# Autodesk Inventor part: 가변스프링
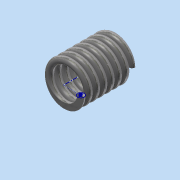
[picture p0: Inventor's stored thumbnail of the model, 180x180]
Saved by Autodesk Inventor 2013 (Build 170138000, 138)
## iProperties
Created: 2019-11
Part Number: 가변스프링
Material: 스테인리스강
Document SubType Name: Modeling
Designer: Administrator
Density: 8.08 g/cm^3
Mass: 19.5517 g
Surface Area: 32.9547 cm^2
Volume: 2.41976 cm^3
Author: Administrator
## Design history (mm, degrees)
sketch "스케치1"
  geometry: L1 (0, 0)-(8, 0); L2 (8, 0)-(8, 23.5); L3 (8, 23.5)-(0, 23.5); L4 (0, 23.5)-(0, 0); C1 r 1.5 at (8, 0)
  constraints: 8 end point, 2 parallel, 1 centre point, 1 coincident, 1 horizontal, 1 perpendicular
  dimensions: "d0" = 16 diameter of L2 L4; "d2" = 23.5 distance between parallel lines of L1 L3 (derived); "d3" = 3 diameter of C1
feature "코일1" pitch "d4" = 10; turns "d6" = 7; dims "d5" = 23.5 (= d2), "d7" = 0, angle "d8" = 90 deg, angle "d9" = 90 deg, "d10" = 0, "d11" = 0
sketch "스케치2"
  geometry: L1 (-9.5, 0)-(-6.5, 0) reference; 1 further point
  constraints: 1 horizontal alignment
extrude "돌출1" cut sketch "스케치2" stored distance "d12" = 10; taper "d13" = 0 deg
node "작업 평면1"
sketch "스케치3"
  geometry: L1 (1.5, 0)-(-1.5, 0) reference; 1 further point
  constraints: 1 horizontal alignment
extrude "돌출2" cut sketch "스케치3" stored distance "d15" = 10; taper "d16" = 0 deg
node "솔리드1"
node "절단 모서리 투영1"
node "절단 모서리 투영2"
other parameters: "d14" = 90 deg
